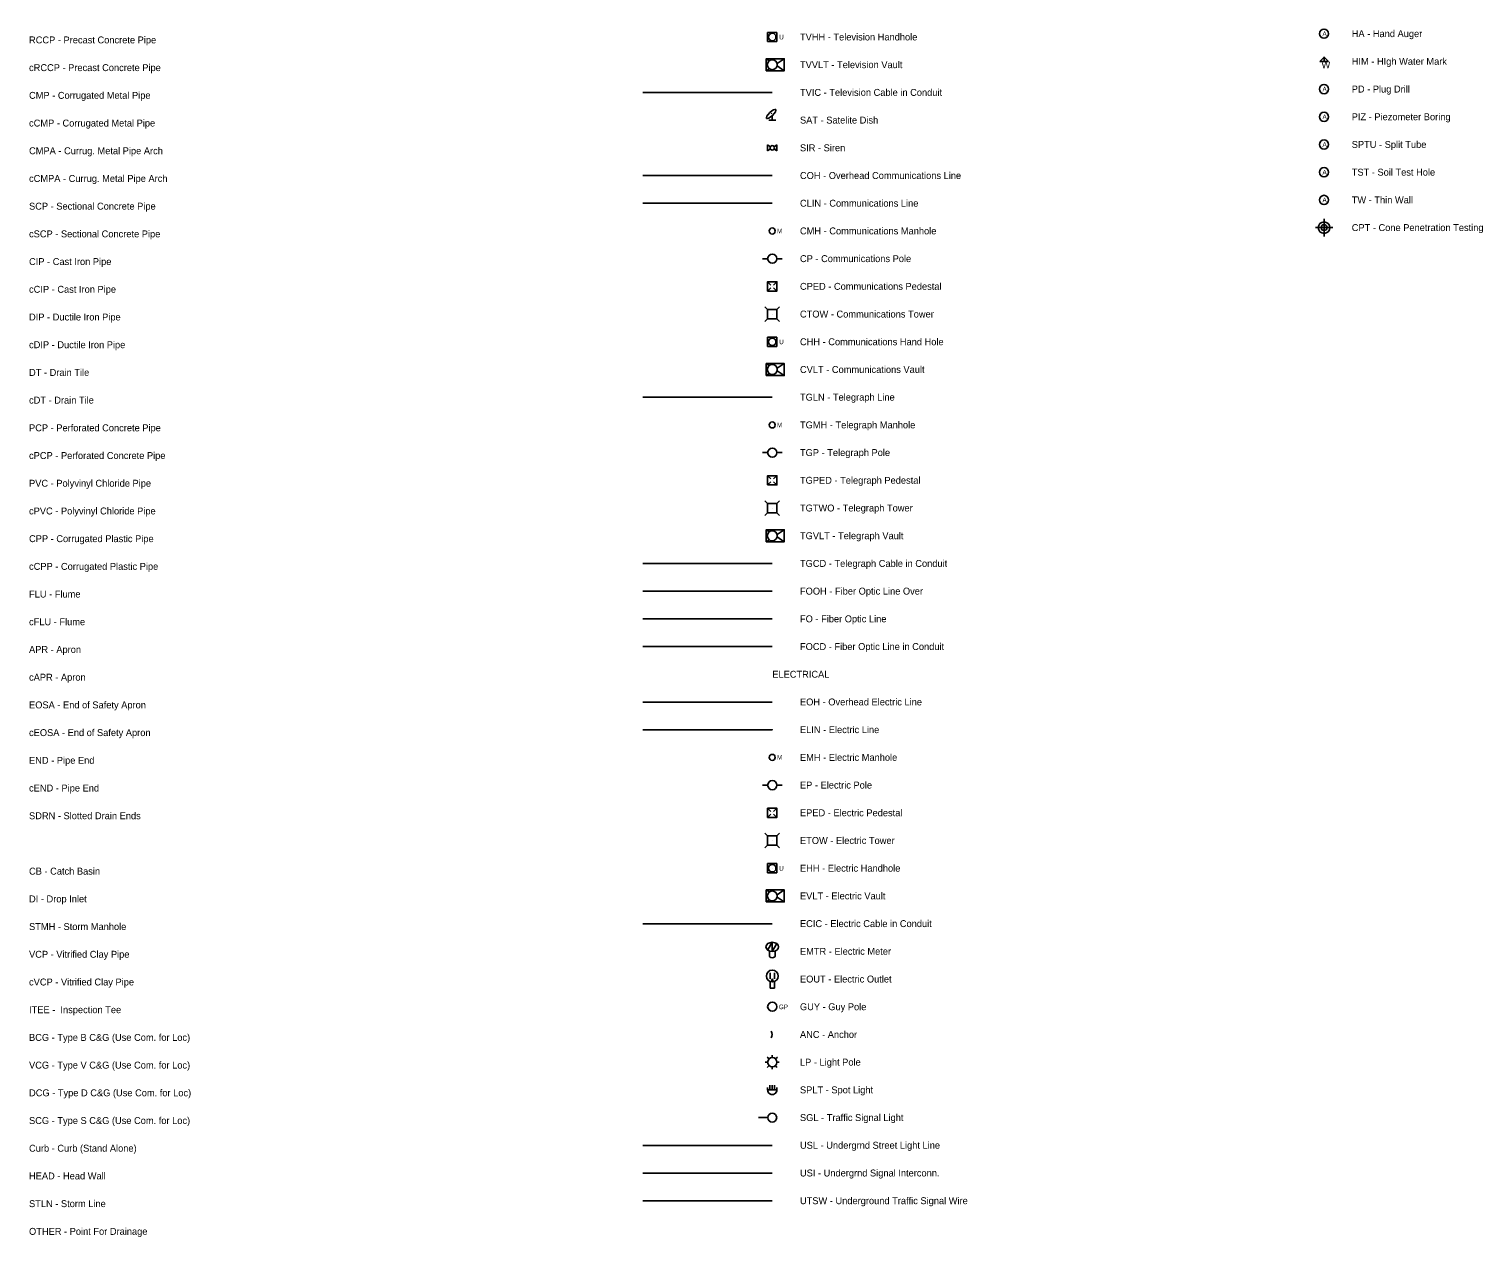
# Model space of a CAD drawing. Extents: x 2147716 to 2176321, y 2125040 to 2131750.
# Drawn here: x 2165474 to 2167048, y 2127378 to 2128686 of the extents above; entities that cross this region are included whole.
import ezdxf

# ---------------------------------------------------------------- set-up
doc = ezdxf.new("R2010")
doc.units = 0
for name, color, linetype in [('BORE HOLE DIST INP', 7, 'Continuous'), ('COMM LIN INP', 7, 'Continuous'), ('COMM PT INP', 7, 'Continuous'), ('Default', 7, 'Continuous'), ('MANMD STRU INP', 7, 'Continuous'), ('PWR LIN INP', 7, 'Continuous'), ('PWR LIN OVHD INP', 7, 'Continuous'), ('PWR PT INP', 7, 'Continuous')]:
    doc.layers.add(name, color=color, linetype=linetype)

msp = doc.modelspace()

# ---------------------------------------------------------------- linework, layer by layer
at = {"layer": 'BORE HOLE DIST INP'}
for p, q in [((2166876.3, 2128655.6), (2166881, 2128650.9)), ((2166876.3, 2128650.9), (2166881, 2128650.9)), ((2166876.3, 2128470.9), (2166876.3, 2128480.3)), ((2166876.3, 2128477.1), (2166876.3, 2128474)), ((2166876.3, 2128470.9), (2166866.9, 2128470.9)), ((2166873.2, 2128470.9), (2166870.1, 2128470.9)), ((2166876.3, 2128470.9), (2166876.3, 2128461.5)), ((2166876.3, 2128470.9), (2166885.7, 2128470.9)), ((2166876.3, 2128464.7), (2166876.3, 2128467.8)), ((2166879.4, 2128470.9), (2166882.5, 2128470.9))]:
    msp.add_line(p, q, dxfattribs=at)
msp.add_lwpolyline([(2166871.6, 2128650.9), (2166876.3, 2128655.6), (2166876.3, 2128650.9)], close=True, dxfattribs=at)
for points in [[(2166873.2, 2128470.9), (2166876.3, 2128470.9), (2166876.3, 2128474)], [(2166879.4, 2128470.9), (2166876.3, 2128470.9), (2166876.3, 2128467.8)]]:
    msp.add_lwpolyline(points, dxfattribs=at)
for centre, radius in [((2166876.3, 2128680.9), 5), ((2166876.3, 2128620.9), 5), ((2166876.3, 2128590.9), 5), ((2166876.3, 2128560.9), 5), ((2166876.3, 2128530.9), 5), ((2166876.3, 2128500.9), 5), ((2166876.3, 2128470.9), 6.25)]:
    msp.add_circle(centre, radius, dxfattribs=at)
for radius, start, end in [(6.25, 0, 90), (6.25, 180, 270), (3.13, 90, 180), (3.13, 180, 270), (3.13, 0, 90), (3.13, 270, 0)]:
    msp.add_arc((2166876.3, 2128470.9), radius, start, end, dxfattribs=at)
at = {"layer": 'COMM LIN INP'}
for p, q in [((2166138.9, 2128617.3), (2166278.9, 2128617.3)), ((2166138.9, 2128527.3), (2166278.9, 2128527.3)), ((2166138.9, 2128497.3), (2166278.9, 2128497.3)), ((2166138.9, 2128287.3), (2166278.9, 2128287.3)), ((2166138.9, 2128107.3), (2166278.9, 2128107.3)), ((2166138.9, 2128077.3), (2166278.9, 2128077.3)), ((2166138.9, 2128047.3), (2166278.9, 2128047.3)), ((2166138.9, 2128017.3), (2166278.9, 2128017.3))]:
    msp.add_line(p, q, dxfattribs=at)
at = {"layer": 'COMM PT INP'}
for p, q in [((2166278.9, 2128677.3), (2166278.9, 2128677.3)), ((2166272.4, 2128653.8), (2166275.7, 2128651.6)), ((2166291.9, 2128653.8), (2166284.1, 2128648.6)), ((2166275.7, 2128643), (2166272.4, 2128640.8)), ((2166284.1, 2128646), (2166291.9, 2128640.8)), ((2166275, 2128587.3), (2166282.8, 2128587.3)), ((2166278.3, 2128594.2), (2166277.7, 2128594.8)), ((2166278.9, 2128587.3), (2166278.9, 2128592.1)), ((2166273.9, 2128560.5), (2166273.9, 2128554.1)), ((2166276.9, 2128558.4), (2166273.9, 2128560.5)), ((2166276.9, 2128556.2), (2166273.9, 2128554.1)), ((2166280.9, 2128558.4), (2166283.9, 2128560.5)), ((2166280.9, 2128556.2), (2166283.9, 2128554.1)), ((2166283.9, 2128560.5), (2166283.9, 2128554.1)), ((2166273.9, 2128437.3), (2166268.3, 2128437.3)), ((2166283.9, 2128437.3), (2166289.5, 2128437.3)), ((2166273.9, 2128412.3), (2166277.4, 2128408.8)), ((2166280.4, 2128408.8), (2166283.9, 2128412.3)), ((2166273.9, 2128402.3), (2166277.4, 2128405.8)), ((2166278.9, 2128407.3), (2166278.9, 2128407.3)), ((2166280.4, 2128405.8), (2166283.9, 2128402.3)), ((2166270.9, 2128385.3), (2166273.9, 2128382.3)), ((2166286.9, 2128385.3), (2166283.9, 2128382.3)), ((2166273.9, 2128372.3), (2166270.9, 2128369.3)), ((2166278.9, 2128377.3), (2166278.9, 2128377.3)), ((2166283.9, 2128372.3), (2166286.9, 2128369.3)), ((2166278.9, 2128347.3), (2166278.9, 2128347.3)), ((2166272.4, 2128323.8), (2166275.7, 2128321.6)), ((2166291.9, 2128323.8), (2166284.1, 2128318.6)), ((2166275.7, 2128313), (2166272.4, 2128310.8)), ((2166284.1, 2128316), (2166291.9, 2128310.8)), ((2166273.9, 2128227.3), (2166268.3, 2128227.3)), ((2166283.9, 2128227.3), (2166289.5, 2128227.3)), ((2166273.9, 2128202.3), (2166277.4, 2128198.8)), ((2166273.9, 2128192.3), (2166277.4, 2128195.8)), ((2166278.9, 2128197.3), (2166278.9, 2128197.3)), ((2166280.4, 2128198.8), (2166283.9, 2128202.3)), ((2166280.4, 2128195.8), (2166283.9, 2128192.3)), ((2166270.9, 2128175.3), (2166273.9, 2128172.3)), ((2166273.9, 2128162.3), (2166270.9, 2128159.3)), ((2166278.9, 2128167.3), (2166278.9, 2128167.3)), ((2166286.9, 2128175.3), (2166283.9, 2128172.3)), ((2166283.9, 2128162.3), (2166286.9, 2128159.3)), ((2166272.4, 2128143.8), (2166275.7, 2128141.6)), ((2166275.7, 2128133), (2166272.4, 2128130.8)), ((2166291.9, 2128143.8), (2166284.1, 2128138.6)), ((2166284.1, 2128136), (2166291.9, 2128130.8))]:
    msp.add_line(p, q, dxfattribs=at)
for points in [[(2166273.9, 2128682.3), (2166283.9, 2128682.3)], [(2166273.9, 2128682.3), (2166273.9, 2128672.3)], [(2166283.9, 2128682.3), (2166283.9, 2128672.3)], [(2166273.9, 2128672.3), (2166283.9, 2128672.3)], [(2166273.9, 2128352.3), (2166283.9, 2128352.3)], [(2166273.9, 2128352.3), (2166273.9, 2128342.3)], [(2166283.9, 2128352.3), (2166283.9, 2128342.3)], [(2166273.9, 2128342.3), (2166283.9, 2128342.3)]]:
    msp.add_lwpolyline(points, dxfattribs=at)
for points in [[(2166272.4, 2128640.8), (2166291.9, 2128640.8), (2166291.9, 2128653.8), (2166272.4, 2128653.8)], [(2166273.9, 2128402.3), (2166283.9, 2128402.3), (2166283.9, 2128412.3), (2166273.9, 2128412.3)], [(2166273.9, 2128372.3), (2166283.9, 2128372.3), (2166283.9, 2128382.3), (2166273.9, 2128382.3)], [(2166272.4, 2128310.8), (2166291.9, 2128310.8), (2166291.9, 2128323.8), (2166272.4, 2128323.8)], [(2166273.9, 2128192.3), (2166283.9, 2128192.3), (2166283.9, 2128202.3), (2166273.9, 2128202.3)], [(2166273.9, 2128162.3), (2166283.9, 2128162.3), (2166283.9, 2128172.3), (2166273.9, 2128172.3)], [(2166272.4, 2128130.8), (2166291.9, 2128130.8), (2166291.9, 2128143.8), (2166272.4, 2128143.8)]]:
    msp.add_lwpolyline(points, close=True, dxfattribs=at)
for centre, radius in [((2166278.9, 2128677.3), 4.01), ((2166278.9, 2128647.3), 5.4), ((2166278.9, 2128557.3), 2.38), ((2166278.8, 2128467.3), 3.31), ((2166278.9, 2128437.3), 5), ((2166278.9, 2128347.3), 4.01), ((2166278.9, 2128317.3), 5.4), ((2166278.8, 2128257.3), 3.31), ((2166278.9, 2128227.3), 5), ((2166278.9, 2128137.3), 5.4)]:
    msp.add_circle(centre, radius, dxfattribs=at)
msp.add_ellipse((2166277.7, 2128594), major_axis=(-4.99, -4.74), ratio=0.30554, dxfattribs=at)
at = {"layer": 'MANMD STRU INP'}
msp.add_line((2166274.1, 2127507.3), (2166263.9, 2127507.3), dxfattribs=at)
msp.add_circle((2166278.9, 2127507.3), 4.76, dxfattribs=at)
at = {"layer": 'PWR LIN INP'}
for p, q in [((2166138.9, 2127927.3), (2166278.9, 2127927.3)), ((2166138.9, 2127717.3), (2166278.9, 2127717.3)), ((2166138.9, 2127477.3), (2166278.9, 2127477.3)), ((2166138.9, 2127447.3), (2166278.9, 2127447.3)), ((2166138.9, 2127417.3), (2166278.9, 2127417.3))]:
    msp.add_line(p, q, dxfattribs=at)
at = {"layer": 'PWR LIN OVHD INP'}
msp.add_line((2166278.9, 2127957.3), (2166138.9, 2127957.3), dxfattribs=at)
at = {"layer": 'PWR PT INP'}
for p, q in [((2166278.8, 2127927.1), (2166279, 2127927.5)), ((2166278.8, 2127927.5), (2166279, 2127927.1)), ((2166273.9, 2127867.3), (2166268.3, 2127867.3)), ((2166283.9, 2127867.3), (2166289.5, 2127867.3)), ((2166273.9, 2127842.3), (2166277.4, 2127838.8)), ((2166273.9, 2127832.3), (2166277.4, 2127835.8)), ((2166278.9, 2127837.3), (2166278.9, 2127837.3)), ((2166280.4, 2127838.8), (2166283.9, 2127842.3)), ((2166280.4, 2127835.8), (2166283.9, 2127832.3)), ((2166270.9, 2127815.3), (2166273.9, 2127812.3)), ((2166286.9, 2127815.3), (2166283.9, 2127812.3)), ((2166273.9, 2127802.3), (2166270.9, 2127799.3)), ((2166278.9, 2127807.3), (2166278.9, 2127807.3)), ((2166283.9, 2127802.3), (2166286.9, 2127799.3)), ((2166278.9, 2127777.3), (2166278.9, 2127777.3)), ((2166272.4, 2127753.8), (2166275.7, 2127751.6)), ((2166291.9, 2127753.8), (2166284.1, 2127748.6)), ((2166275.7, 2127743), (2166272.4, 2127740.8)), ((2166284.1, 2127746), (2166291.9, 2127740.8)), ((2166274.1, 2127688.8), (2166278.9, 2127697.1)), ((2166275.9, 2127687.8), (2166275.9, 2127682.2)), ((2166278.9, 2127697.1), (2166278.9, 2127687.3)), ((2166278.9, 2127687.3), (2166283.8, 2127695.7)), ((2166281.9, 2127687.8), (2166281.9, 2127682.2)), ((2166276.5, 2127664.2), (2166276.5, 2127657.4)), ((2166281.3, 2127664.2), (2166281.3, 2127657.4)), ((2166276.5, 2127647.6), (2166276.5, 2127654.7)), ((2166276.5, 2127647.6), (2166281.3, 2127647.6)), ((2166281.3, 2127647.6), (2166281.3, 2127654.7)), ((2166271.3, 2127567.3), (2166273.9, 2127567.3)), ((2166275.4, 2127570.8), (2166273.4, 2127572.9)), ((2166273.4, 2127561.7), (2166275.4, 2127563.8)), ((2166278.9, 2127572.3), (2166278.9, 2127574.9)), ((2166278.9, 2127567.3), (2166278.9, 2127567.3)), ((2166278.9, 2127559.7), (2166278.9, 2127562.3)), ((2166282.4, 2127570.8), (2166284.5, 2127572.9)), ((2166284, 2127561.7), (2166282.4, 2127563.8)), ((2166284, 2127567.3), (2166286.5, 2127567.3)), ((2166273.9, 2127537.3), (2166273.9, 2127539.8)), ((2166273.9, 2127537.3), (2166283.9, 2127537.3)), ((2166276.4, 2127537.3), (2166276.4, 2127542.3)), ((2166278.9, 2127537.3), (2166278.9, 2127542.3)), ((2166278.9, 2127537.3), (2166278.9, 2127537.3)), ((2166281.4, 2127537.3), (2166281.4, 2127542.3)), ((2166283.9, 2127537.3), (2166283.9, 2127539.8))]:
    msp.add_line(p, q, dxfattribs=at)
for points in [[(2166273.9, 2127832.3), (2166283.9, 2127832.3), (2166283.9, 2127842.3), (2166273.9, 2127842.3)], [(2166273.9, 2127802.3), (2166283.9, 2127802.3), (2166283.9, 2127812.3), (2166273.9, 2127812.3)], [(2166272.4, 2127740.8), (2166291.9, 2127740.8), (2166291.9, 2127753.8), (2166272.4, 2127753.8)]]:
    msp.add_lwpolyline(points, close=True, dxfattribs=at)
for points in [[(2166273.9, 2127782.3), (2166283.9, 2127782.3)], [(2166273.9, 2127782.3), (2166273.9, 2127772.3)], [(2166283.9, 2127782.3), (2166283.9, 2127772.3)], [(2166273.9, 2127772.3), (2166283.9, 2127772.3)]]:
    msp.add_lwpolyline(points, dxfattribs=at)
for centre, radius in [((2166278.8, 2127897.3), 3.31), ((2166278.9, 2127867.3), 5), ((2166278.9, 2127777.3), 4.01), ((2166278.9, 2127747.3), 5.4), ((2166278.9, 2127660.6), 6.39), ((2166278.9, 2127656.4), 0.9), ((2166278.9, 2127627.4), 5), ((2166278.9, 2127567.3), 5)]:
    msp.add_circle(centre, radius, dxfattribs=at)
for centre, radius, start, end in [((2166272.6, 2127597.3), 6.29, 324.6924, 35.1858), ((2166278.9, 2127537.3), 5, 179.996, 0.004)]:
    msp.add_arc(centre, radius, start, end, dxfattribs=at)
msp.add_ellipse((2166278.9, 2127692.2), major_axis=(-6.9, 0), ratio=0.710145, dxfattribs=at)
msp.add_ellipse((2166278.9, 2127682.2), major_axis=(-3, 0), ratio=0.602742, start_param=0, end_param=3.141593, dxfattribs=at)

# ---------------------------------------------------------------- texts
at = {"layer": 'BORE HOLE DIST INP'}
for s, height, p in [('A', 5, (2166874.6, 2128678.4)), ('W', 7.5, (2166873.6, 2128643.3)), ('A', 5, (2166874.6, 2128618.4)), ('A', 5, (2166874.6, 2128588.4)), ('A', 5, (2166874.6, 2128558.4)), ('A', 5, (2166874.6, 2128528.4)), ('A', 5, (2166874.6, 2128498.4))]:
    msp.add_text(s, height=height, dxfattribs=at).set_placement(p)
at = {"layer": 'COMM PT INP'}
for s, p in [('U', (2166286.3, 2128674.7)), ('M', (2166284, 2128464.8)), ('U', (2166286.3, 2128344.7)), ('M', (2166284, 2128254.8))]:
    msp.add_text(s, height=5, dxfattribs=at).set_placement(p)
at = {"layer": 'Default'}
for s, p in [('TVHH - Television Handhole', (2166308.9, 2128673.6)), ('HA - Hand Auger', (2166906.3, 2128677.2)), ('RCCP - Precast Concrete Pipe', (2165474.2, 2128670.4)), ('cRCCP - Precast Concrete Pipe', (2165474.2, 2128640.4)), ('TVVLT - Television Vault', (2166308.9, 2128643.6)), ('HIM - HIgh Water Mark', (2166906.3, 2128647.2)), ('CMP - Corrugated Metal Pipe', (2165474.2, 2128610.4)), ('TVIC - Television Cable in Conduit', (2166308.9, 2128613.6)), ('PD - Plug Drill', (2166906.3, 2128617.2)), ('cCMP - Corrugated Metal Pipe', (2165474.2, 2128580.4)), ('SAT - Satelite Dish', (2166308.9, 2128583.6)), ('PIZ - Piezometer Boring', (2166906.3, 2128587.2)), ('CMPA - Currug. Metal Pipe Arch', (2165474.2, 2128550.4)), ('SIR - Siren', (2166308.9, 2128553.6)), ('SPTU - Split Tube', (2166906.3, 2128557.2)), ('cCMPA - Currug. Metal Pipe Arch', (2165474.2, 2128520.4)), ('COH - Overhead Communications Line', (2166308.9, 2128523.6)), ('TST - Soil Test Hole', (2166906.3, 2128527.2)), ('SCP - Sectional Concrete Pipe', (2165474.2, 2128490.4)), ('CLIN - Communications Line', (2166308.9, 2128493.6)), ('TW - Thin Wall', (2166906.3, 2128497.2)), ('CPT - Cone Penetration Testing', (2166906.3, 2128467.2)), ('cSCP - Sectional Concrete Pipe', (2165474.2, 2128460.4)), ('CMH - Communications Manhole', (2166308.9, 2128463.6)), ('CIP - Cast Iron Pipe', (2165474.2, 2128430.4)), ('CP - Communications Pole', (2166308.9, 2128433.6)), ('cCIP - Cast Iron Pipe', (2165474.2, 2128400.4)), ('CPED - Communications Pedestal', (2166308.9, 2128403.6)), ('CTOW - Communications Tower', (2166308.9, 2128373.6)), ('DIP - Ductile Iron Pipe', (2165474.2, 2128370.4)), ('CHH - Communications Hand Hole', (2166308.9, 2128343.6)), ('cDIP - Ductile Iron Pipe', (2165474.2, 2128340.4)), ('DT - Drain Tile', (2165474.2, 2128310.4)), ('CVLT - Communications Vault', (2166308.9, 2128313.6)), ('cDT - Drain Tile', (2165474.2, 2128280.4)), ('TGLN - Telegraph Line', (2166308.9, 2128283.6)), ('PCP - Perforated Concrete Pipe', (2165474.2, 2128250.4)), ('TGMH - Telegraph Manhole', (2166308.9, 2128253.6)), ('cPCP - Perforated Concrete Pipe', (2165474.2, 2128220.4)), ('TGP - Telegraph Pole', (2166308.9, 2128223.6)), ('PVC - Polyvinyl Chloride Pipe', (2165474.2, 2128190.4)), ('TGPED - Telegraph Pedestal', (2166308.9, 2128193.6)), ('cPVC - Polyvinyl Chloride Pipe', (2165474.2, 2128160.4)), ('TGTWO - Telegraph Tower', (2166308.9, 2128163.6)), ('CPP - Corrugated Plastic Pipe', (2165474.2, 2128130.4)), ('TGVLT - Telegraph Vault', (2166308.9, 2128133.6)), ('cCPP - Corrugated Plastic Pipe', (2165474.2, 2128100.4)), ('TGCD - Telegraph Cable in Conduit', (2166308.9, 2128103.6)), ('FOOH - Fiber Optic Line Over', (2166308.9, 2128073.6)), ('FLU - Flume', (2165474.2, 2128070.4)), ('FO - Fiber Optic Line ', (2166308.9, 2128043.6)), ('cFLU - Flume', (2165474.2, 2128040.4)), ('FOCD - Fiber Optic Line in Conduit', (2166308.9, 2128013.6)), ('APR - Apron', (2165474.2, 2128010.4)), ('cAPR - Apron', (2165474.2, 2127980.4)), ('ELECTRICAL', (2166278.9, 2127983.6)), ('EOSA - End of Safety Apron', (2165474.2, 2127950.4)), ('EOH - Overhead Electric Line', (2166308.9, 2127953.6)), ('cEOSA - End of Safety Apron', (2165474.2, 2127920.4)), ('ELIN - Electric Line', (2166308.9, 2127923.6)), ('END - Pipe End', (2165474.2, 2127890.4)), ('EMH - Electric Manhole', (2166308.9, 2127893.6)), ('cEND - Pipe End', (2165474.2, 2127860.4)), ('EP - Electric Pole', (2166308.9, 2127863.6)), ('SDRN - Slotted Drain Ends', (2165474.2, 2127830.4)), ('EPED - Electric Pedestal', (2166308.9, 2127833.6)), ('ETOW - Electric Tower', (2166308.9, 2127803.6)), ('CB - Catch Basin', (2165474.2, 2127770.4)), ('EHH - Electric Handhole', (2166308.9, 2127773.6)), ('EVLT - Electric Vault', (2166308.9, 2127743.6)), ('DI - Drop Inlet', (2165474.2, 2127740.4)), ('ECIC - Electric Cable in Conduit', (2166308.9, 2127713.6)), ('STMH - Storm Manhole', (2165474.2, 2127710.4)), ('VCP - Vitrified Clay Pipe', (2165474.2, 2127680.4)), ('EMTR - Electric Meter', (2166308.9, 2127683.6)), ('cVCP - Vitrified Clay Pipe', (2165474.2, 2127650.4)), ('EOUT - Electric Outlet', (2166308.9, 2127653.6)), ('ITEE -  Inspection Tee', (2165474.2, 2127620.4)), ('GUY - Guy Pole', (2166308.9, 2127623.6)), ('BCG - Type B C&G (Use Com. for Loc)', (2165474.2, 2127590.4)), ('ANC - Anchor', (2166308.9, 2127593.6)), ('VCG - Type V C&G (Use Com. for Loc)', (2165474.2, 2127560.4)), ('LP - Light Pole', (2166308.9, 2127563.6)), ('DCG - Type D C&G (Use Com. for Loc)', (2165474.2, 2127530.4)), ('SPLT - Spot Light', (2166308.9, 2127533.6)), ('SCG - Type S C&G (Use Com. for Loc)', (2165474.2, 2127500.4)), ('SGL - Traffic Signal Light', (2166308.9, 2127503.6)), ('Curb - Curb (Stand Alone)', (2165474.2, 2127470.4)), ('USL - Undergrnd Street Light Line', (2166308.9, 2127473.6)), ('USI - Undergrnd Signal Interconn.', (2166308.9, 2127443.6)), ('HEAD - Head Wall', (2165474.2, 2127440.4)), ('UTSW - Underground Traffic Signal Wire', (2166308.9, 2127413.6)), ('STLN - Storm Line', (2165474.2, 2127410.4)), ('OTHER - Point For Drainage', (2165474.2, 2127380.4))]:
    msp.add_text(s, height=7.5, dxfattribs=at).set_placement(p)
at = {"layer": 'PWR PT INP'}
for s, p in [('M', (2166284, 2127894.8)), ('U', (2166286.3, 2127774.7)), ('GP', (2166286, 2127624.7))]:
    msp.add_text(s, height=5, dxfattribs=at).set_placement(p)

doc.saveas('drawing.dxf')
